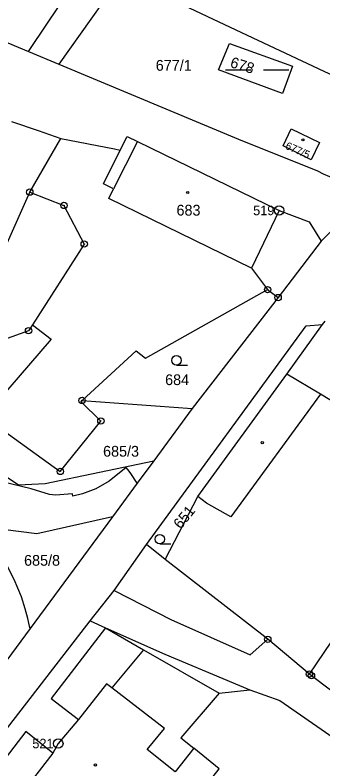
# Model space of a CAD drawing. Extents: x -749778 to -749372, y -967291 to -966955.
# Drawn here: x -749556.3 to -749507.7, y -967221.1 to -967101.9 of the extents above; entities that cross this region are included whole.
import ezdxf

# ---------------------------------------------------------------- set-up
doc = ezdxf.new("R2010")
doc.units = 0
for name, color, linetype in [('Hranice parcel', 7, 'Continuous'), ('Parcelní čísla', 7, 'Continuous'), ('Vnitřní kresba', 7, 'Continuous'), ('Značky bodu BP', 7, 'Continuous'), ('Značky budov', 7, 'Continuous'), ('Značky kultur', 7, 'Continuous')]:
    doc.layers.add(name, color=color, linetype=linetype)

msp = doc.modelspace()

# ---------------------------------------------------------------- linework, layer by layer
at = {"layer": 'Hranice parcel'}
for p, q in [((-749576.24, -967098.5), (-749554.23, -967107.67)), ((-749554.23, -967107.67), (-749549.42, -967109.68)), ((-749554, -967129.9), (-749549.11, -967121.42)), ((-749516.41, -967145.31), (-749514.74, -967146.55)), ((-749514.74, -967146.55), (-749528.34, -967164.11)), ((-749507.71, -967150.81), (-749507.3, -967150.29)), ((-749545.74, -967162.82), (-749528.34, -967164.11)), ((-749528.34, -967164.11), (-749534.4, -967172.34)), ((-749534.4, -967172.34), (-749537.02, -967175.91)), ((-749537.02, -967175.91), (-749540.92, -967181.19)), ((-749540.92, -967181.19), (-749553.95, -967198.86)), ((-749532.62, -967187.94), (-749535.56, -967185.6)), ((-749553.95, -967198.86), (-749569.6, -967220.07))]:
    msp.add_line(p, q, dxfattribs=at)
for points in [[(-749536.81, -967092.95), (-749537.33, -967092.65), (-749549.42, -967109.68)], [(-749536.81, -967092.95), (-749538.87, -967096), (-749521.44, -967104.24), (-749491.04, -967118.52)], [(-749554.23, -967107.67), (-749553.8, -967107.04), (-749549.38, -967100.48)], [(-749522.44, -967106.43), (-749512.48, -967109.98), (-749514.07, -967114.3), (-749524.19, -967110.59), (-749522.44, -967106.43)], [(-749549.42, -967109.68), (-749521.02, -967121.52), (-749508.54, -967126.52)], [(-749556.87, -967118.72), (-749552.69, -967120.13), (-749549.11, -967121.42)], [(-749509.51, -967124.77), (-749513.96, -967122.57), (-749512.69, -967119.91), (-749508.23, -967122.03), (-749509.51, -967124.77)], [(-749549.11, -967121.42), (-749540.6, -967123.03), (-749539.71, -967123.25), (-749538.6, -967121.09), (-749536.99, -967121.88), (-749514.59, -967132.79), (-749518.97, -967141.9), (-749516.41, -967145.31)], [(-749495.53, -967125.22), (-749507.92, -967137.64), (-749514.74, -967146.55)], [(-749508.54, -967126.52), (-749507.61, -967127.01), (-749506.64, -967127.41), (-749505.63, -967127.72), (-749504.6, -967127.93), (-749503.56, -967128.04), (-749502.51, -967128.05), (-749502.18, -967128.03), (-749501.14, -967127.91), (-749500.11, -967127.69), (-749499.11, -967127.38), (-749498.14, -967126.97), (-749497.22, -967126.47), (-749496.34, -967125.89), (-749495.53, -967125.22)], [(-749575.24, -967161.82), (-749562.35, -967148.01), (-749561.39, -967146.09), (-749559.94, -967143.18), (-749554, -967129.9)], [(-749554, -967129.9), (-749548.6, -967132), (-749545.4, -967138.1), (-749553.6, -967150.87), (-749554.2, -967151.8), (-749560.25, -967154), (-749563.2, -967151.9), (-749568.8, -967159.2), (-749561.22, -967165.4), (-749549.18, -967174.04), (-749542.77, -967166.07), (-749545.93, -967163), (-749545.74, -967162.82)], [(-749545.74, -967162.82), (-749537.19, -967154.99), (-749535.71, -967156.16), (-749516.41, -967145.31)], [(-749535.56, -967185.6), (-749510.32, -967151.05), (-749507.71, -967150.81)], [(-749532.62, -967187.94), (-749527.44, -967178), (-749513.39, -967158.64), (-749507.71, -967150.81)], [(-749509.79, -967206.06), (-749488, -967173.92), (-749482.75, -967163.3)], [(-749580.28, -967171.75), (-749574.93, -967170.19), (-749566.54, -967170.41), (-749561.52, -967172.29), (-749555.8, -967176.14), (-749551.55, -967175.94), (-749534.4, -967172.34)], [(-749537.02, -967175.91), (-749538.03, -967174.36), (-749538.28, -967173.97), (-749538.76, -967173.43), (-749541.48, -967175.55), (-749543.56, -967176.77), (-749545.65, -967177.56), (-749547.19, -967177.95), (-749547.26, -967177.59), (-749549.92, -967177.81), (-749550.89, -967177.68), (-749553.79, -967176.8), (-749558.39, -967175.68), (-749560.79, -967175.03), (-749562.93, -967175.31), (-749563.04, -967175.46), (-749563.04, -967175.6), (-749568.49, -967173.77), (-749571.33, -967173.01), (-749574.23, -967172.55), (-749581.95, -967172.24)], [(-749540.92, -967181.19), (-749552.88, -967183.89), (-749558.28, -967183.21), (-749565.92, -967178.54), (-749568.07, -967177.26), (-749572.83, -967177.39)], [(-749553.95, -967198.86), (-749554.04, -967198.48), (-749554.32, -967197.29), (-749554.75, -967195.73), (-749555.32, -967193.83), (-749556.46, -967191.11), (-749557.79, -967188.52), (-749558.73, -967187.21), (-749559.52, -967186.11), (-749560.17, -967185.38), (-749561.59, -967184.04), (-749562.48, -967183.46), (-749563.86, -967182.82), (-749568.6, -967181.36), (-749570.54, -967180.87), (-749571.89, -967180.6)], [(-749544.44, -967197.63), (-749540.67, -967192.84), (-749535.56, -967185.6)], [(-749509.79, -967206.06), (-749516.38, -967200.56), (-749532.62, -967187.94)], [(-749576.96, -967239.3), (-749574.4, -967236.29), (-749544.44, -967197.63)], [(-749544.44, -967197.63), (-749542.05, -967198.77), (-749532.66, -967202.89), (-749519.24, -967208.54), (-749514.5, -967210.26), (-749496.94, -967222.41)], [(-749493.61, -967217.22), (-749506.47, -967208.63), (-749509.47, -967206.32), (-749509.79, -967206.06)], [(-749547.13, -967251.19), (-749539.73, -967241.65), (-749548.27, -967234.85), (-749542.52, -967227.63), (-749538.01, -967231.22), (-749539.89, -967233.59), (-749535.96, -967236.61), (-749531.53, -967230.62), (-749532.42, -967229.96), (-749530.45, -967227.43), (-749529.58, -967228.12), (-749524.04, -967221.02), (-749528.05, -967217.79), (-749531.02, -967221.51), (-749535.46, -967217.96), (-749532.69, -967214.65), (-749541.02, -967208.23), (-749541.86, -967207.58), (-749546.28, -967213.26), (-749549.5, -967217.04), (-749550.38, -967218.55), (-749560.87, -967232.04), (-749564.94, -967237.28)]]:
    msp.add_lwpolyline(points, dxfattribs=at)
at = {"layer": 'Vnitřní kresba'}
for p, q in [((-749536.99, -967121.88), (-749540.75, -967129.37)), ((-749542.36, -967128.56), (-749539.71, -967123.25)), ((-749540.75, -967129.37), (-749542.36, -967128.56)), ((-749541.52, -967130.91), (-749540.75, -967129.37)), ((-749518.97, -967141.9), (-749541.52, -967130.91)), ((-749514.59, -967132.79), (-749509.86, -967134.6)), ((-749509.86, -967134.6), (-749507.92, -967137.64)), ((-749553.6, -967150.87), (-749550.63, -967153.13)), ((-749550.63, -967153.13), (-749561.22, -967165.4)), ((-749508.05, -967161.85), (-749513.39, -967158.64)), ((-749508.05, -967161.85), (-749522.2, -967181.2)), ((-749488, -967173.92), (-749508.05, -967161.85)), ((-749526.07, -967179.07), (-749527.44, -967178)), ((-749522.2, -967181.2), (-749526.07, -967179.07)), ((-749540.67, -967192.84), (-749531.72, -967197.46)), ((-749531.72, -967197.46), (-749519.14, -967203.02)), ((-749542.05, -967198.77), (-749550.61, -967209.92)), ((-749542.05, -967198.77), (-749536.05, -967202.21)), ((-749519.14, -967203.02), (-749516.38, -967200.56)), ((-749536.05, -967202.21), (-749541.02, -967208.23)), ((-749536.05, -967202.21), (-749524.09, -967209.08)), ((-749524.09, -967209.08), (-749519.24, -967208.54)), ((-749550.61, -967209.92), (-749546.28, -967213.26)), ((-749524.09, -967209.08), (-749530.1, -967216.14)), ((-749554.64, -967215.12), (-749572.33, -967238.1)), ((-749550.38, -967218.55), (-749554.64, -967215.12)), ((-749530.1, -967216.14), (-749528.05, -967217.79))]:
    msp.add_line(p, q, dxfattribs=at)
at = {"layer": 'Značky bodu BP'}
for centre, radius in [((-749554, -967129.9), 0.5), ((-749554, -967129.9), 0.0303), ((-749548.6, -967132), 0.5), ((-749548.6, -967132), 0.0303), ((-749514.59, -967132.79), 0.75), ((-749514.59, -967132.79), 0.03), ((-749545.4, -967138.1), 0.5), ((-749545.4, -967138.1), 0.0303), ((-749516.41, -967145.31), 0.5), ((-749516.41, -967145.31), 0.0303), ((-749514.74, -967146.55), 0.5), ((-749514.74, -967146.55), 0.0303), ((-749554.2, -967151.8), 0.5), ((-749554.2, -967151.8), 0.0303), ((-749545.74, -967162.82), 0.5), ((-749545.74, -967162.82), 0.0303), ((-749542.77, -967166.07), 0.5), ((-749542.77, -967166.07), 0.0303), ((-749549.18, -967174.04), 0.5), ((-749549.18, -967174.04), 0.0303), ((-749516.38, -967200.56), 0.5), ((-749516.38, -967200.56), 0.0303), ((-749509.79, -967206.06), 0.5), ((-749509.47, -967206.32), 0.5), ((-749509.79, -967206.06), 0.0303), ((-749509.47, -967206.32), 0.0303), ((-749549.5, -967217.04), 0.75), ((-749549.5, -967217.04), 0.03)]:
    msp.add_circle(centre, radius, dxfattribs=at)
at = {"layer": 'Značky budov'}
for centre in [(-749510.83, -967121.63), (-749529.04, -967129.96), (-749517.25, -967169.48), (-749543.64, -967220.42)]:
    msp.add_circle(centre, 0.175, dxfattribs=at)
at = {"layer": 'Značky kultur'}
for p, q in [((-749523.09, -967110.57), (-749519.07, -967110.57)), ((-749517.06, -967110.57), (-749513.04, -967110.57)), ((-749530.82, -967157.23), (-749529.07, -967157.23)), ((-749533.45, -967185.49), (-749531.7, -967185.49))]:
    msp.add_line(p, q, dxfattribs=at)
for centre in [(-749530.82, -967156.48), (-749533.45, -967184.74)]:
    msp.add_circle(centre, 0.75, dxfattribs=at)

# ---------------------------------------------------------------- texts
at = {"layer": 'Parcelní čísla'}
for s, height, rotation, p in [('678', 1.7, 343, (-749522.45, -967110.11)), ('677/5', 1.2, 336, (-749513.71, -967123)), ('651', 1.7, 51, (-749530.14, -967183.26))]:
    msp.add_text(s, height=height, rotation=rotation, dxfattribs=at).set_placement(p)
for s, p in [('677/1', (-749534.09, -967110.71)), ('683', (-749530.81, -967133.6)), ('684', (-749532.61, -967160.39)), ('685/3', (-749542.42, -967171.7)), ('685/8', (-749554.91, -967188.94))]:
    msp.add_text(s, height=1.7, dxfattribs=at).set_placement(p)
at = {"layer": 'Značky bodu BP'}
for s, p in [('519', (-749518.69, -967133.54)), ('521', (-749553.6, -967217.79))]:
    msp.add_text(s, height=1.5, dxfattribs=at).set_placement(p)

doc.saveas('drawing.dxf')
